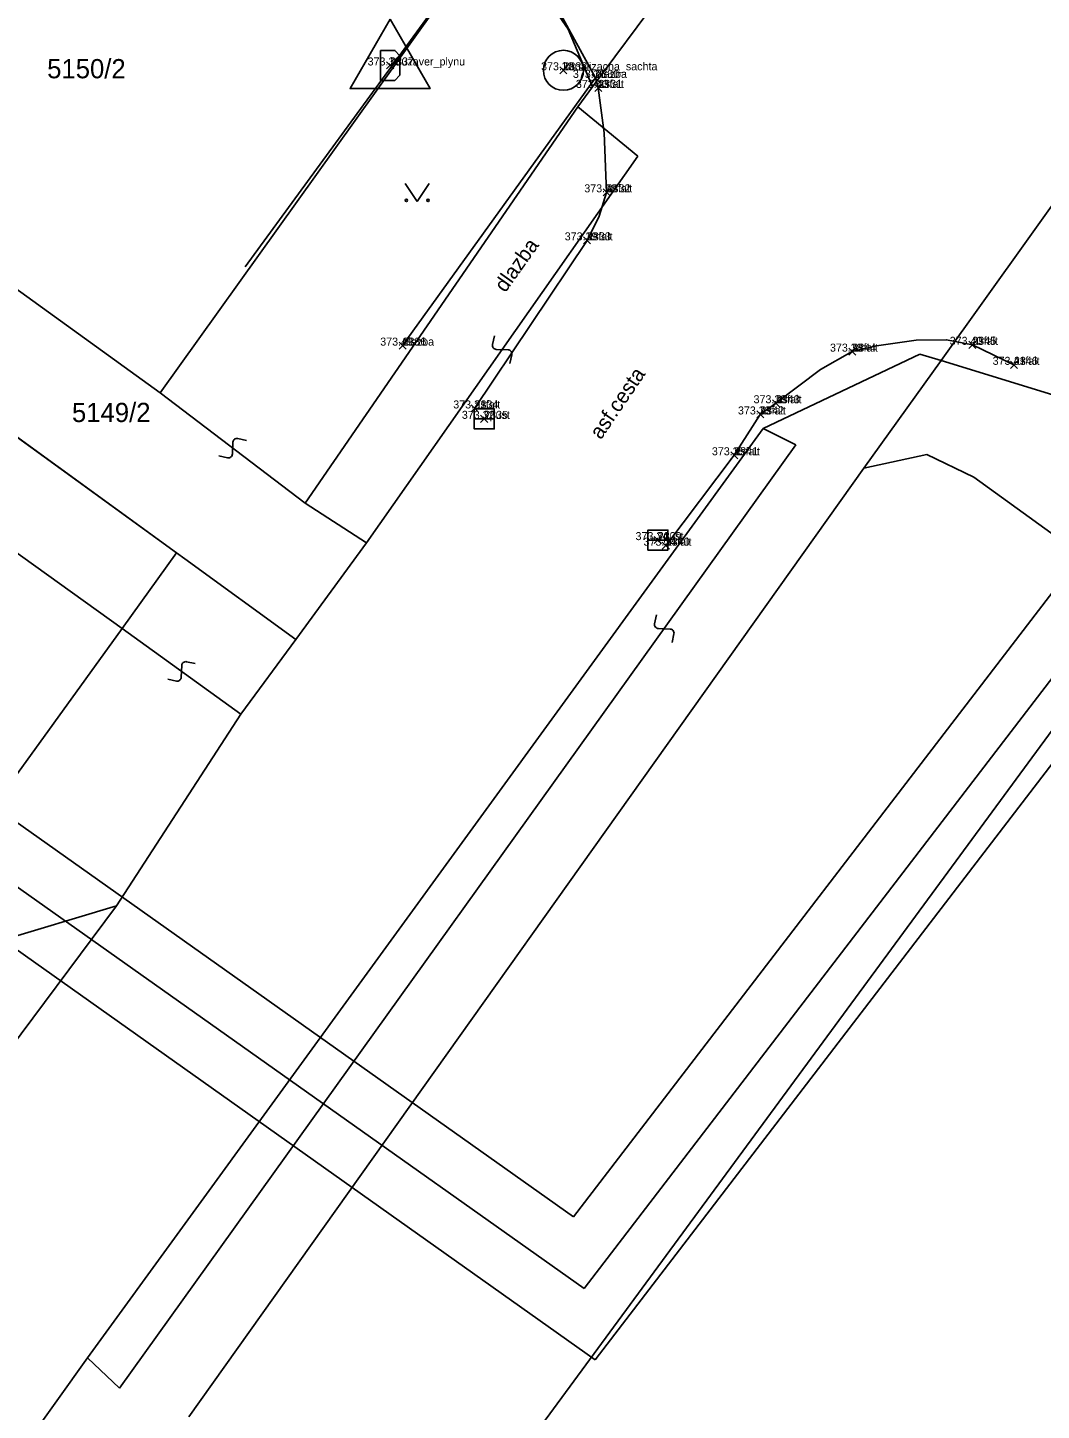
# Model space of a CAD drawing. Extents: x -400488 to -400124, y -1251493 to -1251223.
# Drawn here: x -400314.45 to -400289.12, y -1251434.41 to -1251399.85 of the extents above; entities that cross this region are included whole.
import ezdxf

# ---------------------------------------------------------------- set-up
doc = ezdxf.new("R2010")
doc.units = 0
for name, color, linetype in [('Level 20', 7, 'Continuous'), ('Level 21', 7, 'Continuous'), ('Level 22', 7, 'Continuous'), ('Level 23', 7, 'Continuous'), ('Level 31', 7, 'Continuous'), ('Level 32', 7, 'Continuous'), ('Level 34', 7, 'Continuous'), ('Level 36', 7, 'Continuous'), ('Level 50', 7, 'Continuous'), ('Level 52', 7, 'Continuous'), ('Level 63', 7, 'Continuous')]:
    doc.layers.add(name, color=color, linetype=linetype)

msp = doc.modelspace()

# ---------------------------------------------------------------- linework, layer by layer
at = {"layer": 'Level 20'}
for p, q in [((-400305.478, -1251400.888), (-400305.302, -1251400.712)), ((-400305.302, -1251400.888), (-400305.478, -1251400.712)), ((-400301.148, -1251401.008), (-400300.972, -1251400.832)), ((-400300.972, -1251401.008), (-400301.148, -1251400.832)), ((-400300.348, -1251401.198), (-400300.172, -1251401.022)), ((-400300.172, -1251401.198), (-400300.348, -1251401.022)), ((-400300.278, -1251401.448), (-400300.102, -1251401.272)), ((-400300.102, -1251401.448), (-400300.278, -1251401.272)), ((-400300.068, -1251404.058), (-400299.892, -1251403.882)), ((-400299.892, -1251404.058), (-400300.068, -1251403.882)), ((-400300.558, -1251405.258), (-400300.382, -1251405.082)), ((-400300.382, -1251405.258), (-400300.558, -1251405.082)), ((-400305.168, -1251407.888), (-400304.992, -1251407.712)), ((-400304.992, -1251407.888), (-400305.168, -1251407.712)), ((-400293.928, -1251408.038), (-400293.752, -1251407.862)), ((-400293.752, -1251408.038), (-400293.928, -1251407.862)), ((-400290.928, -1251407.868), (-400290.752, -1251407.692)), ((-400290.752, -1251407.868), (-400290.928, -1251407.692)), ((-400289.888, -1251408.368), (-400289.712, -1251408.192)), ((-400289.712, -1251408.368), (-400289.888, -1251408.192)), ((-400303.368, -1251409.458), (-400303.192, -1251409.282)), ((-400303.192, -1251409.458), (-400303.368, -1251409.282)), ((-400295.838, -1251409.328), (-400295.662, -1251409.152)), ((-400295.662, -1251409.328), (-400295.838, -1251409.152)), ((-400303.128, -1251409.718), (-400302.952, -1251409.542)), ((-400302.952, -1251409.718), (-400303.128, -1251409.542)), ((-400296.228, -1251409.608), (-400296.052, -1251409.432)), ((-400296.052, -1251409.608), (-400296.228, -1251409.432)), ((-400296.878, -1251410.628), (-400296.702, -1251410.452)), ((-400296.702, -1251410.628), (-400296.878, -1251410.452)), ((-400298.788, -1251412.748), (-400298.612, -1251412.572)), ((-400298.612, -1251412.748), (-400298.788, -1251412.572)), ((-400298.588, -1251412.888), (-400298.412, -1251412.712)), ((-400298.412, -1251412.888), (-400298.588, -1251412.712))]:
    msp.add_line(p, q, dxfattribs=at)
at = {"layer": 'Level 31'}
msp.add_lwpolyline([(-400300.26, -1251401.11), (-400305.08, -1251407.8)], dxfattribs=at)
at = {"layer": 'Level 32'}
for points in [[(-400301.89, -1251398.51), (-400301.4, -1251398.9), (-400301.31, -1251399.19), (-400300.26, -1251401.11), (-400300.19, -1251401.36), (-400300.045, -1251402.48), (-400299.98, -1251403.97), (-400300.164, -1251404.567), (-400300.47, -1251405.17), (-400303.28, -1251409.37)], [(-400298.5, -1251412.8), (-400296.79, -1251410.54), (-400296.14, -1251409.52), (-400295.75, -1251409.24), (-400294.636, -1251408.396), (-400293.84, -1251407.95), (-400293.232, -1251407.805), (-400292.244, -1251407.662), (-400291.484, -1251407.655), (-400290.84, -1251407.78), (-400289.8, -1251408.28)]]:
    msp.add_lwpolyline(points, dxfattribs=at)
at = {"layer": 'Level 34'}
msp.add_lwpolyline([(-400333.76, -1251378.15), (-400304.338, -1251399.434), (-400304.338, -1251399.434), (-400309.014, -1251405.829)], dxfattribs=at)
at = {"layer": 'Level 36'}
for q in [(-400305.014, -1251403.752), (-400304.414, -1251403.752)]:
    msp.add_line((-400304.714, -1251404.202), q, dxfattribs=at)
for centre in [(-400304.984, -1251404.172), (-400304.444, -1251404.172)]:
    msp.add_circle(centre, 0.03, dxfattribs=at)
at = {"layer": 'Level 50'}
msp.add_lwpolyline([(-400305.39, -1251399.646), (-400306.39, -1251401.377), (-400304.39, -1251401.377)], close=True, dxfattribs=at)
msp.add_lwpolyline([(-400305.635, -1251400.425), (-400305.269, -1251400.425), (-400305.145, -1251400.561), (-400305.145, -1251401.039), (-400305.269, -1251401.175), (-400305.635, -1251401.175), (-400305.635, -1251400.425)], dxfattribs=at)
at = {"layer": 'Level 52'}
for points in [[(-400303.29, -1251409.63), (-400303.29, -1251409.38), (-400302.79, -1251409.38), (-400302.79, -1251409.63)], [(-400298.95, -1251412.66), (-400298.95, -1251412.41), (-400298.45, -1251412.41), (-400298.45, -1251412.66)]]:
    msp.add_lwpolyline(points, dxfattribs=at)
for points in [[(-400303.29, -1251409.63), (-400302.79, -1251409.63), (-400302.79, -1251409.88), (-400303.29, -1251409.88)], [(-400298.95, -1251412.66), (-400298.45, -1251412.66), (-400298.45, -1251412.91), (-400298.95, -1251412.91)]]:
    msp.add_lwpolyline(points, close=True, dxfattribs=at)
msp.add_circle((-400301.06, -1251400.92), 0.5, dxfattribs=at)
at = {"layer": 'Level 63'}
for p, q in [((-400343.89, -1251392), (-400312.09, -1251414.87)), ((-400312.09, -1251414.87), (-400343.89, -1251392)), ((-400300.33, -1251401.33), (-400296.03, -1251395.53)), ((-400296.03, -1251395.53), (-400300.33, -1251401.33)), ((-400300.94, -1251399.89), (-400301.53, -1251399.04)), ((-400301.53, -1251399.04), (-400300.94, -1251399.89)), ((-400304.29, -1251399.42), (-400311.14, -1251408.98)), ((-400311.14, -1251408.98), (-400304.29, -1251399.42)), ((-400300.33, -1251401.33), (-400300.94, -1251399.89)), ((-400300.94, -1251399.89), (-400300.33, -1251401.33)), ((-400341.41, -1251400.8), (-400300.81, -1251429.57)), ((-400300.7, -1251401.83), (-400300.33, -1251401.33)), ((-400300.33, -1251401.33), (-400300.7, -1251401.83)), ((-400300.27, -1251433.14), (-400345.06, -1251401.4)), ((-400311.14, -1251408.98), (-400321.44, -1251401.55)), ((-400321.44, -1251401.55), (-400311.14, -1251408.98)), ((-400307.51, -1251411.74), (-400300.7, -1251401.83)), ((-400300.7, -1251401.83), (-400307.51, -1251411.74)), ((-400299.2, -1251403.07), (-400300.7, -1251401.83)), ((-400305.98, -1251412.73), (-400299.2, -1251403.07)), ((-400291.62, -1251408.17), (-400288.01, -1251403.12)), ((-400288.01, -1251403.12), (-400291.62, -1251408.17)), ((-400323.17, -1251403.95), (-400310.73, -1251412.98)), ((-400310.73, -1251412.98), (-400323.17, -1251403.95)), ((-400335.53, -1251406.59), (-400300.54, -1251431.36)), ((-400302.831, -1251407.773), (-400302.783, -1251407.555)), ((-400302.443, -1251407.906), (-400302.737, -1251407.894)), ((-400302.397, -1251408.245), (-400302.349, -1251408.027)), ((-400292.15, -1251408.01), (-400296.07, -1251409.87)), ((-400293.55, -1251410.86), (-400291.62, -1251408.17)), ((-400291.62, -1251408.17), (-400293.55, -1251410.86)), ((-400291.62, -1251408.17), (-400292.15, -1251408.01)), ((-400291.62, -1251408.17), (-400288.72, -1251409.06)), ((-400311.14, -1251408.98), (-400307.51, -1251411.74)), ((-400296.07, -1251409.87), (-400312.95, -1251433.09)), ((-400296.07, -1251409.87), (-400295.25, -1251410.28)), ((-400295.25, -1251410.28), (-400312.15, -1251433.85)), ((-400309.331, -1251410.507), (-400309.319, -1251410.213)), ((-400309.198, -1251410.119), (-400308.98, -1251410.167)), ((-400309.67, -1251410.553), (-400309.452, -1251410.601)), ((-400291.98, -1251410.52), (-400293.55, -1251410.86)), ((-400293.55, -1251410.86), (-400291.98, -1251410.52)), ((-400290.8, -1251411.09), (-400291.98, -1251410.52)), ((-400291.98, -1251410.52), (-400290.8, -1251411.09)), ((-400293.55, -1251410.86), (-400310.42, -1251434.57)), ((-400310.42, -1251434.57), (-400293.55, -1251410.86)), ((-400250.32, -1251440.37), (-400290.8, -1251411.09)), ((-400290.8, -1251411.09), (-400250.32, -1251440.37)), ((-400300.81, -1251429.57), (-400287.04, -1251411.61)), ((-400305.98, -1251412.73), (-400307.51, -1251411.74)), ((-400307.51, -1251411.74), (-400305.98, -1251412.73)), ((-400307.75, -1251415.14), (-400305.98, -1251412.73)), ((-400305.98, -1251412.73), (-400307.75, -1251415.14)), ((-400310.73, -1251412.98), (-400312.09, -1251414.87)), ((-400312.09, -1251414.87), (-400310.73, -1251412.98)), ((-400310.73, -1251412.98), (-400310.52, -1251413.13)), ((-400310.52, -1251413.13), (-400310.73, -1251412.98)), ((-400310.52, -1251413.13), (-400307.75, -1251415.14)), ((-400307.75, -1251415.14), (-400310.52, -1251413.13)), ((-400300.54, -1251431.36), (-400286.78, -1251413.41)), ((-400298.78, -1251414.749), (-400298.733, -1251414.531)), ((-400312.09, -1251414.87), (-400314.7, -1251418.49)), ((-400314.7, -1251418.49), (-400312.09, -1251414.87)), ((-400312.09, -1251414.87), (-400309.12, -1251417.01)), ((-400309.12, -1251417.01), (-400307.75, -1251415.14)), ((-400307.75, -1251415.14), (-400309.12, -1251417.01)), ((-400286.46, -1251415.13), (-400300.27, -1251433.14)), ((-400298.392, -1251414.882), (-400298.686, -1251414.87)), ((-400298.346, -1251415.221), (-400298.298, -1251415.003)), ((-400310.611, -1251416.087), (-400310.599, -1251415.793)), ((-400310.478, -1251415.699), (-400310.26, -1251415.747)), ((-400310.95, -1251416.133), (-400310.732, -1251416.181)), ((-400288.33, -1251416.7), (-400304.56, -1251438.79)), ((-400312.23, -1251421.8), (-400309.12, -1251417.01)), ((-400309.12, -1251417.01), (-400312.23, -1251421.8)), ((-400321.51, -1251434.24), (-400312.23, -1251421.8)), ((-400312.23, -1251421.8), (-400321.51, -1251434.24)), ((-400315.36, -1251422.74), (-400312.23, -1251421.8)), ((-400312.95, -1251433.09), (-400317.46, -1251439.39)), ((-400312.15, -1251433.85), (-400312.95, -1251433.09))]:
    msp.add_line(p, q, dxfattribs=at)
for centre, start, end in [((-400302.733, -1251407.794), 167.7527, 267.7631), ((-400302.447, -1251408.006), 347.753, 87.7631), ((-400309.219, -1251410.217), 77.7527, 177.7631), ((-400309.431, -1251410.503), 257.753, 357.7631), ((-400298.682, -1251414.77), 167.7527, 267.7631), ((-400298.396, -1251414.982), 347.753, 87.7631), ((-400310.499, -1251415.797), 77.7527, 177.7631), ((-400310.711, -1251416.083), 257.753, 357.7631)]:
    msp.add_arc(centre, 0.1, start, end, dxfattribs=at)

# ---------------------------------------------------------------- texts
at = {"layer": 'Level 21'}
for s, p in [('2337', (-400305.39, -1251400.8)), ('2338', (-400301.06, -1251400.92)), ('2330', (-400300.26, -1251401.11)), ('2331', (-400300.19, -1251401.36)), ('2332', (-400299.98, -1251403.97)), ('2333', (-400300.47, -1251405.17)), ('2336', (-400305.08, -1251407.8)), ('2344', (-400293.84, -1251407.95)), ('2345', (-400290.84, -1251407.78)), ('2346', (-400289.8, -1251408.28)), ('2334', (-400303.28, -1251409.37)), ('2343', (-400295.75, -1251409.24)), ('2335', (-400303.04, -1251409.63)), ('2342', (-400296.14, -1251409.52)), ('2341', (-400296.79, -1251410.54)), ('2339', (-400298.7, -1251412.66)), ('2340', (-400298.5, -1251412.8))]:
    msp.add_text(s, height=0.2, dxfattribs=at).set_placement(p)
at = {"layer": 'Level 22'}
for s, p in [('hl.uzaver_plynu', (-400305.39, -1251400.8)), ('kanalizacna_sachta', (-400301.06, -1251400.92)), ('dlazba', (-400300.26, -1251401.11)), ('asfalt', (-400300.19, -1251401.36)), ('asfalt', (-400299.98, -1251403.97)), ('asfalt', (-400300.47, -1251405.17)), ('dlazba', (-400305.08, -1251407.8)), ('asfalt', (-400293.84, -1251407.95)), ('asfalt', (-400290.84, -1251407.78)), ('asfalt', (-400289.8, -1251408.28)), ('asfalt', (-400303.28, -1251409.37)), ('asfalt', (-400295.75, -1251409.24)), ('vpust', (-400303.04, -1251409.63)), ('asfalt', (-400296.14, -1251409.52)), ('asfalt', (-400296.79, -1251410.54)), ('vpust', (-400298.7, -1251412.66)), ('asfalt', (-400298.5, -1251412.8))]:
    msp.add_text(s, height=0.2, dxfattribs=at).set_placement(p)
at = {"layer": 'Level 23'}
for s, p in [('373.36', (-400305.953, -1251400.8)), ('373.38', (-400301.618, -1251400.92)), ('373.36', (-400300.823, -1251401.11)), ('373.43', (-400300.748, -1251401.36)), ('373.38', (-400300.538, -1251403.97)), ('373.39', (-400301.028, -1251405.17)), ('373.49', (-400305.638, -1251407.8)), ('373.38', (-400294.398, -1251407.95)), ('373.40', (-400291.406, -1251407.78)), ('373.41', (-400290.333, -1251408.28)), ('373.31', (-400303.813, -1251409.37)), ('373.38', (-400296.308, -1251409.24)), ('373.32', (-400303.598, -1251409.63)), ('373.33', (-400296.698, -1251409.52)), ('373.35', (-400297.349, -1251410.54)), ('373.34', (-400299.258, -1251412.66)), ('373.34', (-400299.058, -1251412.8))]:
    msp.add_text(s, height=0.2, dxfattribs=at).set_placement(p)
at = {"layer": 'Level 31'}
msp.add_text('dlazba', height=0.375, rotation=54.566, dxfattribs=at).set_placement((-400302.512, -1251406.494))
at = {"layer": 'Level 32'}
msp.add_text('asf.cesta', height=0.375, rotation=55.8347, dxfattribs=at).set_placement((-400300.123, -1251410.167))
at = {"layer": 'Level 63'}
msp.add_text('5150/2', height=0.48, dxfattribs=at).set_placement((-400313.962, -1251401.12))
msp.add_text('5149/2', height=0.48, rotation=0.01, dxfattribs=at).set_placement((-400313.342, -1251409.71))

doc.saveas('drawing.dxf')
